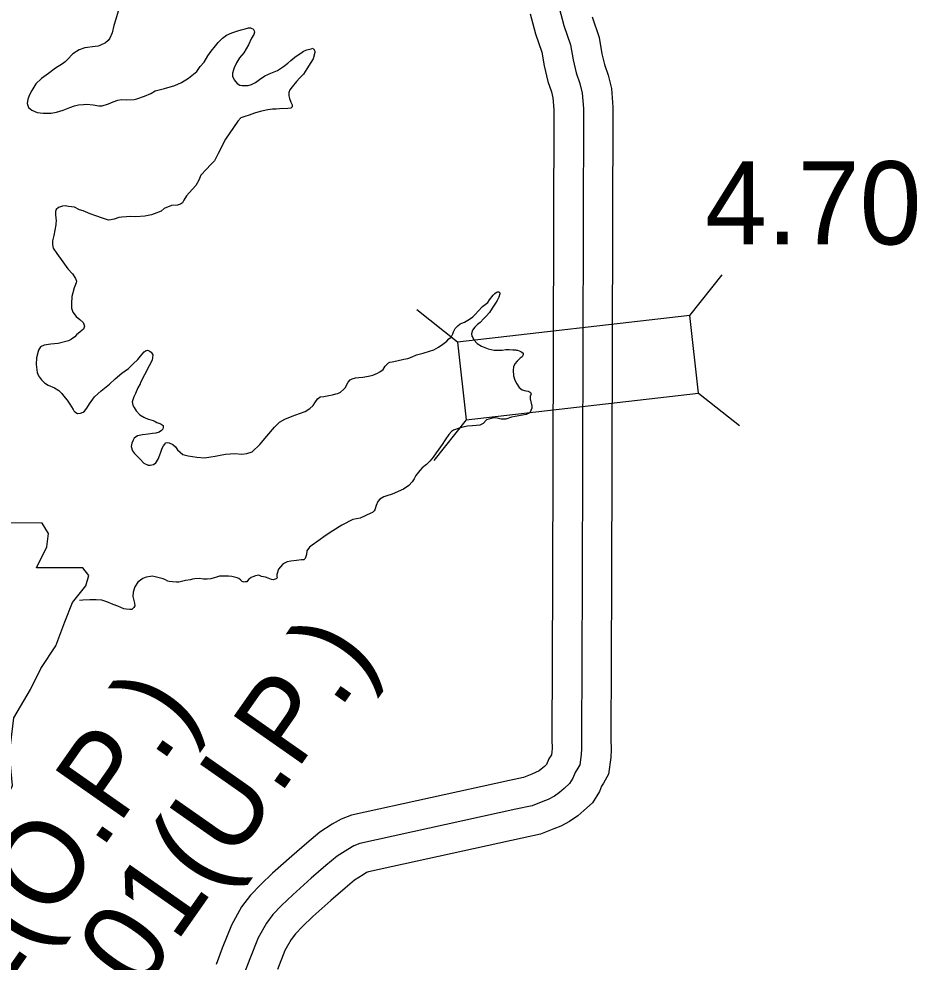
# Model space of a CAD drawing. Extents: x 31699 to 244310, y -8841 to 11474.
# Drawn here: x 100753.7 to 101057.8, y 3092.6 to 3411.9 of the extents above; entities that cross this region are included whole.
import ezdxf

# ---------------------------------------------------------------- set-up
doc = ezdxf.new("R2010")
doc.units = 0
for name, color, linetype in [('B_Logo', 7, 'Continuous'), ('G-ANNO-TEXT', 7, 'Continuous'), ('R_Draft', 7, 'Continuous'), ('R_XS_EARTHWORK_STAGE1', 7, 'Continuous'), ('R_XS_EARTHWORK_STAGE2', 7, 'Continuous'), ('S_WALL', 7, 'Continuous')]:
    doc.layers.add(name, color=color, linetype=linetype)

msp = doc.modelspace()

# ---------------------------------------------------------------- linework, layer by layer
at = {"layer": 'B_Logo'}
msp.add_lwpolyline([(100936.67, 3415.64), (100938.22, 3409.65), (100940.45, 3403.08), (100941.32, 3398.01), (100942.39, 3393.56), (100943.64, 3390.04), (100944.42, 3386.71), (100944.83, 3381.58), (100944.39, 3221.79), (100944.18, 3168.04), (100944.23, 3164.77), (100944.13, 3162.83), (100943.64, 3159.41), (100943, 3158.2), (100942.08, 3156.79), (100941.31, 3154.9), (100940.14, 3153.02), (100938.3, 3151.38), (100936.79, 3150.03), (100935.01, 3148.8), (100932.9, 3147.69), (100931.11, 3146.93), (100927.47, 3145.54), (100921.96, 3144.32), (100869.19, 3132.74), (100867.14, 3131.97), (100865.02, 3130.74), (100861.46, 3128.48), (100857.65, 3125.28), (100852.71, 3121), (100846.4, 3115.36), (100842.66, 3111.76), (100839.71, 3108.71), (100837.49, 3105.8), (100834.7, 3100.82), (100831.87, 3093.69), (100830.02, 3088.72)], dxfattribs=at)
at = {"layer": 'G-ANNO-TEXT'}
msp.add_lwpolyline([(100670.28, 3241.25), (100674.85, 3210.8), (100672.82, 3164.61), (100676.88, 3162.07), (100684.49, 3162.07), (100684.49, 3145.83), (100748.44, 3145.83), (100751.49, 3152.43), (100750.47, 3163.09), (100752, 3175.27), (100757.58, 3184.91), (100761.13, 3192.02), (100766.21, 3199.63), (100769.25, 3207.75), (100771.79, 3214.35), (100776.36, 3219.93), (100777.37, 3223.49), (100775.34, 3226.02), (100759.61, 3226.02), (100763.16, 3233.13), (100763.67, 3237.7), (100761.56, 3241.2)], close=True, dxfattribs=at)
at = {"layer": 'R_Draft'}
for points in [[(100787.26, 3414.43), (100786.5, 3411.81), (100785.86, 3409.66), (100785.3, 3407.18), (100784.53, 3405.3), (100783.94, 3404.49), (100783.02, 3403.74), (100781.1, 3402.84), (100780.51, 3402.63), (100779.51, 3402.55), (100775.99, 3402.03), (100774.13, 3401.33), (100771.95, 3400.03), (100771.49, 3399.62), (100770.58, 3398.54), (100769.4, 3397.32), (100768.41, 3396.7), (100766.1, 3395.2), (100763.73, 3393.36), (100761.29, 3391.72), (100759.38, 3389.88), (100758.02, 3387.59), (100757.31, 3386.18), (100756.73, 3384.63), (100756.49, 3383.23)], [(100756.49, 3383.23), (100756.91, 3381.9), (100758.05, 3380.92), (100759.86, 3380.21), (100761.86, 3379.91), (100764.59, 3379.95), (100766.39, 3380.24), (100768.64, 3381.01), (100770.89, 3381.92), (100772.48, 3382.48), (100773.87, 3382.77), (100775.6, 3382.93), (100776.73, 3382.94), (100778.87, 3382.78), (100780.74, 3382.41), (100781.94, 3382.43), (100783.99, 3383.06), (100785.58, 3383.82), (100787.17, 3384.31), (100788.43, 3384.6), (100790.16, 3384.49), (100792.76, 3384.6), (100793.62, 3384.81), (100796.2, 3385.72), (100798.32, 3386.62), (100799.84, 3387.45), (100802.96, 3388.3), (100806.54, 3389.36), (100808.79, 3390.33), (100811.16, 3391.83), (100813.93, 3394.08), (100815.1, 3395.7), (100816.41, 3397.26), (100817.71, 3399.35), (100818.75, 3400.96), (100820.32, 3402.79), (100821.18, 3403.81), (100822.69, 3405.3), (100823.94, 3406.32), (100825.79, 3407.15), (100827.84, 3407.85), (100828.9, 3408.2), (100830.3, 3408.49), (100831.49, 3408.84), (100832.09, 3408.79), (100832.56, 3408.66), (100833.03, 3408.47), (100833.37, 3407.87), (100833.51, 3407.34), (100833.19, 3406.53), (100832.47, 3405.32), (100831.44, 3403.1), (100829.82, 3400.4), (100828.44, 3398.71), (100827.34, 3397.03), (100826.56, 3395.28), (100826.37, 3394.61), (100826.06, 3393.47), (100826.07, 3392.47), (100826.62, 3391.21), (100827.64, 3390.02), (100828.51, 3389.43), (100829.31, 3389.31), (100830.71, 3389.27), (100831.38, 3389.34), (100832.5, 3389.7), (100833.76, 3390.38), (100835.21, 3391.34), (100836.99, 3392.57), (100839.04, 3393.54), (100841.22, 3394.44), (100843.34, 3395.74), (100844.79, 3396.83), (100845.77, 3397.72), (100847.15, 3398.87), (100847.88, 3399.42), (100849.13, 3400.31), (100850.05, 3400.92), (100851.18, 3401.41), (100852.7, 3401.76), (100853.23, 3401.91), (100853.3, 3401.77), (100853.57, 3401.64), (100853.71, 3401.38), (100853.85, 3400.98), (100853.85, 3400.51), (100853.29, 3398.37), (100852.57, 3397.09), (100851.21, 3394.93), (100850.03, 3393.18), (100848.85, 3391.89), (100847.74, 3390.67), (100846.17, 3388.91), (100845.45, 3387.9), (100845.06, 3386.96), (100845.08, 3385.82), (100845.29, 3384.89), (100845.78, 3383.63), (100846.19, 3382.77), (100846.27, 3382.1), (100845.74, 3381.62)], [(100845.74, 3381.62), (100844.75, 3381.48), (100841.88, 3381.36), (100840.75, 3381.28), (100839.55, 3381.26), (100837.96, 3381.1), (100835.44, 3380.53), (100833.45, 3379.96), (100831.66, 3379.27), (100830.2, 3378.84), (100828.88, 3378.35), (100827.83, 3377.27), (100826.33, 3375.11), (100823.66, 3371.13), (100821.2, 3366.35), (100819.97, 3363.79), (100818.59, 3362.5), (100817.21, 3361.01), (100815.31, 3358.98), (100814.67, 3357.3), (100813.56, 3355.48), (100811.34, 3352.97), (100810.49, 3351.96), (100809.58, 3350.48), (100809.06, 3349.6), (100808.4, 3349.19), (100807.4, 3348.84), (100805.41, 3348.67), (100802.89, 3347.63), (100801.84, 3346.82), (100799.52, 3345.84), (100798.6, 3345.5), (100796.34, 3345.06), (100793.28, 3344.88), (100791.41, 3344.92), (100790.15, 3344.9), (100788.55, 3344.8), (100787.55, 3344.59), (100785.96, 3344.03), (100784.84, 3343.81), (100784.04, 3343.73), (100781.96, 3344.43), (100779.75, 3345.2), (100777.81, 3345.9), (100775.4, 3346.87), (100774.26, 3347.18), (100772.52, 3348.09), (100771.52, 3348.28), (100770.52, 3348.39), (100769.32, 3348.58), (100768.45, 3348.43), (100767.06, 3348.07), (100766.34, 3347.33), (100766.08, 3346.72), (100766.03, 3345.85), (100766.18, 3344.19), (100766.26, 3343.92), (100766.15, 3342.18), (100765.91, 3340.38), (100765.47, 3338.5), (100765.1, 3336.69), (100765.05, 3335.55), (100765.27, 3334.22), (100766.49, 3332.44), (100768.6, 3329.6), (100770.3, 3327.22), (100771.79, 3325.58), (100772.88, 3323.99), (100773.16, 3323.06), (100773.1, 3322.53), (100772.46, 3320.78), (100771.63, 3317.9), (100771.6, 3317.55)], [(100771.6, 3317.55), (100771.46, 3315.82), (100771.49, 3313.96), (100771.91, 3312.63), (100773.06, 3311.18), (100774.35, 3310.06), (100775.43, 3309.08), (100775.7, 3308.55), (100775.91, 3307.88), (100775.52, 3306.87), (100774.47, 3305.99), (100773.22, 3304.97), (100772.63, 3304.29), (100771.51, 3303.47), (100770.46, 3302.92), (100767.01, 3302), (100764.55, 3301.76), (100762.22, 3301.46), (100760.96, 3300.84), (100760.31, 3299.76), (100759.62, 3297.14), (100759.59, 3294.87), (100759.89, 3292.14), (100760.38, 3291.08), (100761.39, 3289.69), (100762.34, 3288.64), (100763.55, 3287.92), (100765.76, 3286.96), (100767.17, 3286.04), (100768.19, 3285.06)], [(100843.7, 3276.43), (100846.28, 3277.34), (100848.66, 3278.24), (100850.58, 3279.01), (100852.23, 3280.04), (100853.29, 3280.99), (100853.94, 3281.93), (100854.92, 3283.35), (100854.98, 3283.42), (100855.71, 3283.9), (100856.9, 3284.05), (100858.63, 3284.34), (100859.89, 3284.63), (100861.02, 3284.91), (100861.68, 3285.06), (100862.61, 3285.54), (100863.66, 3286.36), (100864.25, 3287.1), (100864.64, 3287.84), (100865.22, 3288.92), (100865.88, 3289.66), (100866.54, 3290.01), (100867.66, 3290.36), (100868.79, 3290.51), (100870.19, 3290.6), (100872.05, 3290.9), (100873.51, 3291.32), (100874.3, 3291.6), (100875.17, 3291.95), (100875.96, 3292.36), (100877.01, 3293.24), (100877.66, 3294.32), (100878.84, 3295.48), (100879.31, 3295.62), (100880.04, 3295.83), (100881.63, 3296.12), (100884.09, 3296.63), (100885.41, 3296.91), (100886.87, 3297.47), (100888.33, 3298.1), (100890.58, 3298.73), (100892.7, 3299.37), (100894.23, 3299.86), (100895.75, 3300.75), (100897.26, 3301.77), (100898.58, 3302.73), (100899.3, 3303.54), (100900.02, 3304.16), (100900.67, 3305.3), (100900.8, 3305.9), (100901.38, 3307.11), (100902.3, 3307.93), (100903.15, 3308.61), (100903.62, 3308.82), (100904.61, 3309.23), (100906.26, 3310.2), (100907.45, 3311.02), (100908.24, 3311.76), (100909.22, 3312.98), (100910.72, 3314.54), (100912.44, 3315.9), (100913.02, 3316.71), (100914.33, 3318.4), (100914.86, 3318.94), (100915.25, 3319.22), (100915.78, 3319.43), (100916.18, 3319.5), (100916.58, 3319.1), (100916.59, 3318.77), (100916.21, 3317.7), (100915.62, 3316.55), (100915.04, 3315.67), (100914, 3313.99), (100913.02, 3312.51), (100911.97, 3311.22), (100911.18, 3310.47), (100909.87, 3309.12), (100908.95, 3308.37), (100908.03, 3307.55), (100907.25, 3306.47), (100907, 3305.27), (100907.08, 3304.47), (100907.35, 3304), (100907.69, 3303.27), (100908.85, 3302.02), (100910.32, 3301.05), (100912.6, 3300.21), (100914.67, 3299.78), (100915.94, 3299.73), (100917.34, 3299.75), (100918.53, 3299.91), (100919.66, 3299.92), (100920.93, 3299.88), (100921.86, 3299.89), (100922.2, 3299.76), (100922.53, 3299.7), (100923.6, 3299.32), (100924, 3299.06), (100924.41, 3298.73), (100924.42, 3298.26), (100924.35, 3297.93)], [(100768.19, 3285.06), (100768.8, 3284.27), (100770.09, 3282.75), (100770.97, 3281.5), (100772.06, 3279.64), (100772.34, 3279.25), (100772.67, 3278.85), (100773.48, 3278.26), (100774.55, 3278.35), (100775.41, 3278.76), (100775.87, 3279.1), (100776.72, 3280.05), (100777.63, 3281.53), (100779.33, 3283.9), (100781.56, 3286), (100784.32, 3288.18), (100786.29, 3290.02), (100788.53, 3291.99), (100790.84, 3293.56), (100792.35, 3295.05), (100793.99, 3296.61), (100794.84, 3297.7), (100795.43, 3298.37), (100796.08, 3299.18), (100796.74, 3299.66), (100797.27, 3299.74), (100797.81, 3299.55), (100798.48, 3299.02), (100799.03, 3298.1), (100798.85, 3296.36), (100797.82, 3294.47), (100796.26, 3291.38), (100794.9, 3288.75), (100794.71, 3288.35), (100794, 3286.93), (100793.16, 3285.05), (100792.58, 3283.91), (100792, 3282.23), (100792.29, 3281.1), (100792.7, 3280.37), (100793.45, 3279.25), (100794.67, 3277.8), (100796.01, 3277.02), (100796.68, 3276.69), (100797.62, 3276.37), (100799.15, 3275.93), (100799.89, 3275.54), (100800.43, 3275.28), (100801.43, 3274.9), (100801.84, 3274.64), (100802.58, 3274.25), (100802.58, 3273.65), (100802.39, 3273.04), (100801.94, 3272.5), (100801.21, 3271.96), (100800.02, 3271.6), (100798.95, 3271.52), (100797.42, 3271.3), (100795.56, 3271.07), (100793.9, 3270.71), (100792.78, 3269.89), (100792.33, 3269.28), (100791.94, 3268.27), (100791.69, 3267.13), (100792.18, 3265.67), (100792.79, 3264.81), (100793.87, 3263.76), (100794.75, 3262.84), (100796.04, 3261.53), (100797.51, 3260.81), (100798.18, 3260.76), (100799.31, 3261.04), (100800.03, 3261.59), (100800.81, 3262.87), (100801.39, 3264.35), (100801.71, 3265.22), (100802.16, 3266.56), (100802.61, 3267.3), (100803.07, 3267.91), (100803.46, 3268.32), (100804.12, 3268.53), (100804.53, 3268.34), (100805.87, 3267.76), (100806.68, 3267.03), (100807.42, 3266.04), (100809.25, 3264.47), (100811.05, 3263.96), (100813.99, 3263.48), (100816.59, 3263.32), (100820.11, 3263.84), (100821.9, 3264.2), (100823.63, 3264.5), (100826.82, 3264.75), (100829.15, 3264.58), (100830.88, 3264.74), (100832.67, 3265.37), (100835.3, 3267.82), (100837.59, 3270.66), (100840.21, 3273.7), (100841.91, 3275.33), (100843.7, 3276.43)], [(100924.35, 3297.93), (100924.1, 3297.46), (100923.44, 3296.98), (100922.38, 3296.03), (100921.67, 3295.15), (100921.15, 3294.07), (100921.03, 3293), (100921.19, 3291), (100921.61, 3289.6), (100922.3, 3288.28), (100923.12, 3287.09), (100924.06, 3286.3), (100925.33, 3285.92), (100926.13, 3285.87), (100926.6, 3285.68), (100926.94, 3285.35), (100927.14, 3284.95), (100926.82, 3284.01), (100926.83, 3283.41), (100926.83, 3283.28), (100927.4, 3280.75), (100927.41, 3280.15), (100927.03, 3279.34), (100926.71, 3278.47), (100925.45, 3277.91), (100920.53, 3277.03), (100918.55, 3276.4), (100916.95, 3276.38), (100915.68, 3276.69), (100914.41, 3276.87), (100912.02, 3276.17), (100910.91, 3274.88), (100910.18, 3274.54), (100909.72, 3274.33), (100908.59, 3274.18), (100907.26, 3274.16), (100905.59, 3274.06), (100904, 3273.7), (100902.81, 3273.28), (100900.89, 3272.65), (100900.23, 3272.18), (100899.31, 3271.16), (100898.01, 3269.4), (100897.03, 3267.85), (100895.85, 3266.23), (100894.94, 3264.95), (100893.96, 3263.53), (100892.85, 3262.18), (100891.67, 3261.02), (100890.29, 3259.87), (100889.44, 3258.99), (100888.06, 3257.36), (100887.48, 3256.15), (100886.83, 3255.14), (100885.71, 3253.92), (100883.87, 3252.69), (100880.1, 3251.03), (100878.31, 3250.46), (100877.25, 3250.11), (100875.93, 3249.29), (100875.21, 3248.48), (100874.69, 3247.14), (100874.25, 3245.66), (100873.99, 3245.39), (100873.46, 3244.78), (100872.87, 3244.57), (100869.23, 3242.91), (100866.71, 3242.4), (100863.07, 3240.48), (100859.97, 3238.56), (100857.79, 3237.12), (100854.96, 3235.07), (100852.98, 3233.71), (100852.06, 3233.03), (100851.15, 3231.81), (100851.03, 3230.54), (100850.65, 3229.2), (100850.13, 3228.79), (100849.33, 3228.71), (100847.67, 3228.55), (100845.74, 3228.32), (100844.48, 3228.03), (100843.68, 3227.69), (100842.96, 3227.14), (100841.65, 3225.58), (100841.08, 3223.77), (100841.02, 3223.17), (100841.09, 3222.64), (100840.96, 3222.44), (100840.76, 3222.37), (100840.43, 3222.23), (100839.84, 3222.02), (100839.24, 3222.08), (100838.1, 3222.52), (100837.16, 3222.84), (100835.83, 3223.16), (100834.95, 3223.54), (100833.76, 3223.39), (100832.9, 3223.04), (100832.3, 3222.77), (100831.77, 3222.36)], [(100831.77, 3222.36), (100831.45, 3222.09), (100830.86, 3221.28), (100830.33, 3221.27), (100829.99, 3221.26), (100829.32, 3221.45), (100828.72, 3221.98), (100828.18, 3222.44), (100827.64, 3222.63), (100825.84, 3223.07), (100824.7, 3223.25), (100823.37, 3223.23), (100822.31, 3223.28), (100821.64, 3223.27), (100820.58, 3222.92), (100819.78, 3222.64), (100818.72, 3222.29), (100817.39, 3222.2), (100816.19, 3222.25), (100814.73, 3222.42), (100813.26, 3222.33), (100812.53, 3222.19), (100811.8, 3222.04), (100810.08, 3221.75), (100807.89, 3221.18), (100807.09, 3221.17), (100805.69, 3221.28), (100804.55, 3221.4), (100804.08, 3221.59), (100803.28, 3221.98), (100802.54, 3222.3), (100801.2, 3222.68), (100799.8, 3222.99), (100798.8, 3223.18), (100798.27, 3223.17), (100796.81, 3222.94), (100795.62, 3222.39), (100794.82, 3221.85), (100793.97, 3221.16), (100792.99, 3219.68), (100792.8, 3219.28), (100792.35, 3217.8), (100792.24, 3216.33), (100792.45, 3215.46), (100792.87, 3214.07), (100792.95, 3213.2), (100792.56, 3212.66), (100791.91, 3211.98), (100791.31, 3211.91), (100789.97, 3212.02), (100789.24, 3212.21), (100787.16, 3213.04), (100785.56, 3213.62), (100783.48, 3214.59), (100781.74, 3215.16), (100779.87, 3215.2), (100777.68, 3215.17), (100775.35, 3215.13), (100774.19, 3215.05)]]:
    msp.add_lwpolyline(points, dxfattribs=at)
at = {"layer": 'R_XS_EARTHWORK_STAGE1'}
for p, q in [((100980.85, 3311.42), (100991.8, 3325.2)), ((100902.17, 3302.4), (100888.39, 3313.35)), ((100983.86, 3285.19), (100997.64, 3274.25)), ((100905.17, 3276.17), (100894.23, 3262.39))]:
    msp.add_line(p, q, dxfattribs=at)
msp.add_lwpolyline([(100905.17, 3276.17), (100983.86, 3285.19), (100980.85, 3311.42), (100902.17, 3302.4)], close=True, dxfattribs=at)
at = {"layer": 'R_XS_EARTHWORK_STAGE2'}
for points in [[(100926.86, 3413.62), (100928.64, 3406.79), (100930.73, 3400.61), (100931.52, 3396), (100932.79, 3390.71), (100934.03, 3387.21), (100934.51, 3385.16), (100934.83, 3381.19), (100934.39, 3221.82), (100934.18, 3167.98), (100934.23, 3164.96), (100934.16, 3163.8), (100934.01, 3162.72), (100933.18, 3161.43), (100932.39, 3159.51), (100931.64, 3158.84), (100930.58, 3157.89), (100929.84, 3157.38), (100928.62, 3156.74), (100927.36, 3156.2), (100924.58, 3155.14), (100919.8, 3154.08), (100866.35, 3142.36), (100862.83, 3141.04), (100859.82, 3139.28), (100855.54, 3136.57), (100851.15, 3132.89), (100846.1, 3128.5), (100839.6, 3122.69), (100835.6, 3118.84), (100832.12, 3115.24), (100829.11, 3111.31), (100825.65, 3105.12), (100822.54, 3097.29), (100820.5, 3091.83)], [(100947.81, 3412.51), (100950.17, 3405.55), (100951.12, 3400.03), (100951.99, 3396.4), (100953.25, 3392.86), (100954.33, 3388.26), (100954.83, 3381.96), (100954.39, 3221.76), (100954.18, 3168.09), (100954.23, 3164.57), (100954.09, 3161.86), (100953.3, 3156.26), (100951.62, 3153.13), (100950.99, 3152.15), (100950.25, 3150.34), (100947.87, 3146.5), (100944.96, 3143.93), (100943, 3142.16), (100940.18, 3140.21), (100937.17, 3138.65), (100934.86, 3137.66), (100930.35, 3135.94), (100924.11, 3134.55), (100872.02, 3123.12), (100871.44, 3122.91), (100870.23, 3122.2), (100867.38, 3120.39), (100864.14, 3117.67), (100859.33, 3113.49), (100853.2, 3108.02), (100849.72, 3104.67), (100847.3, 3102.17), (100845.87, 3100.29), (100843.75, 3096.51), (100841.21, 3090.1)]]:
    msp.add_lwpolyline(points, dxfattribs=at)

# ---------------------------------------------------------------- texts
at = {"layer": 'S_WALL'}
msp.add_text('4.70', height=28.16, dxfattribs=at).set_placement((100986.03, 3335.51))
for s, height, p in [('107.01(U.P.)', 28.1599, (100752.93, 3021.76)), ('0.92(O.P.)', 28.16, (100715.46, 3036))]:
    msp.add_text(s, height=height, rotation=55, dxfattribs=at).set_placement(p)

doc.saveas('drawing.dxf')
